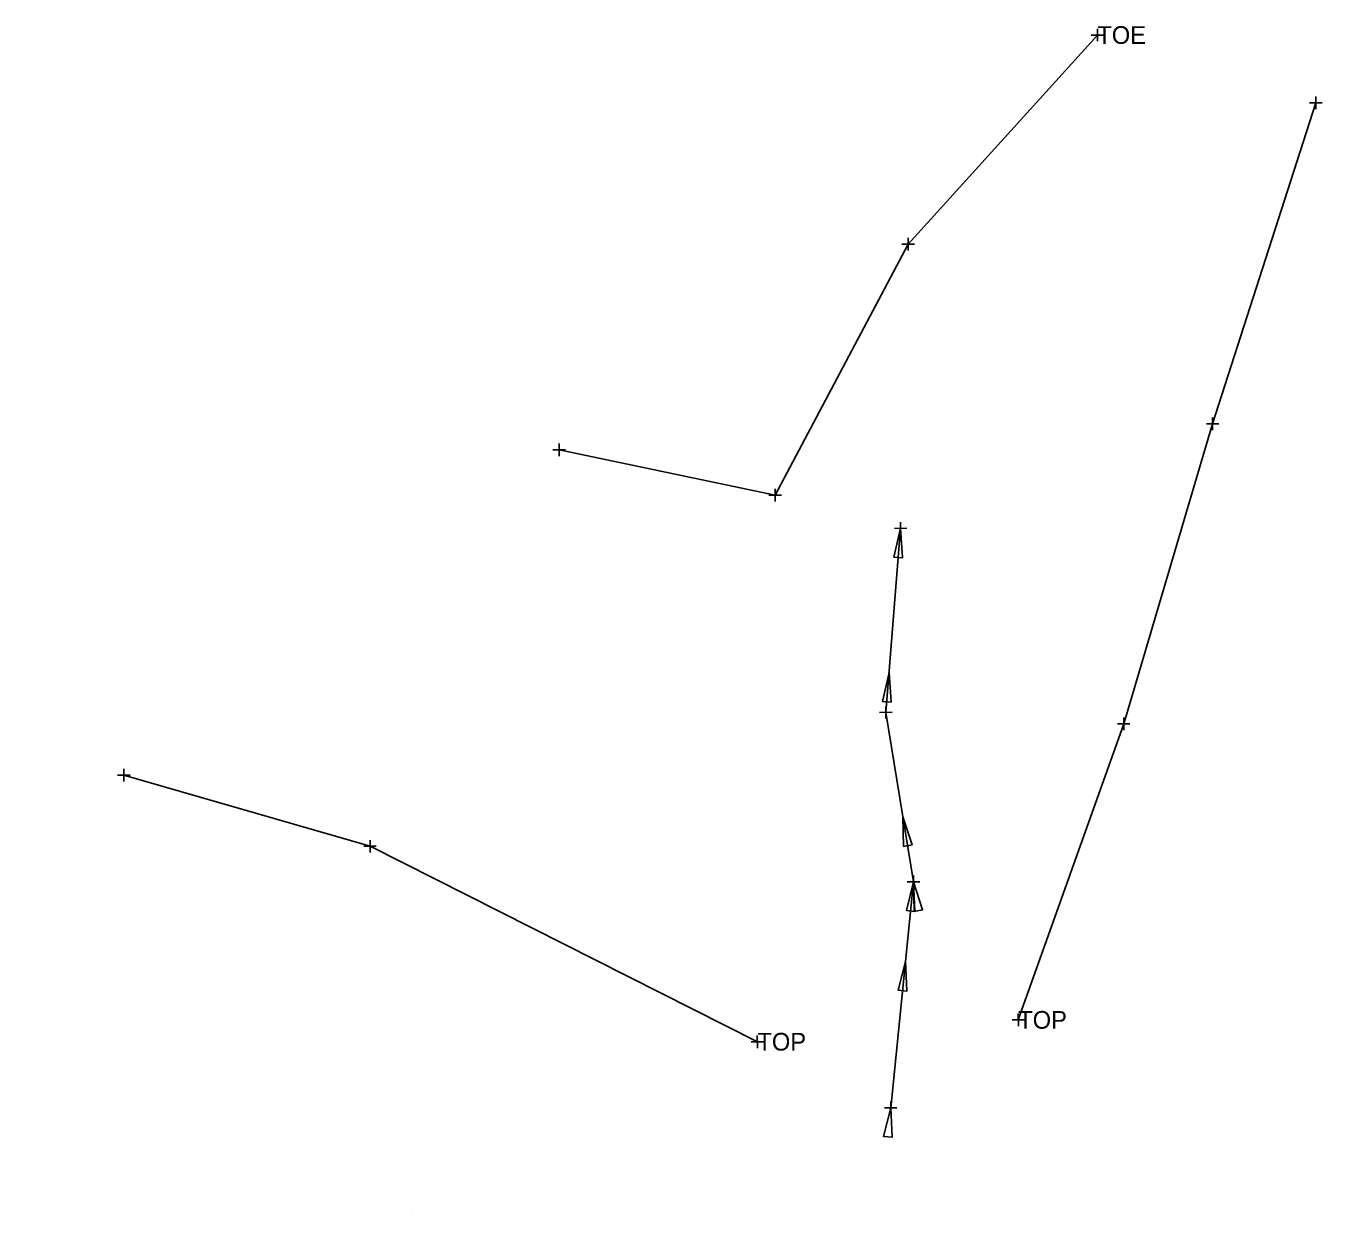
# Model space of a CAD drawing. Extents: x 1733239 to 1734352, y 466612 to 468622.
# Drawn here: x 1733857.5 to 1733989.3, y 468164.4 to 468284.8 of the extents above; entities that cross this region are included whole.
import ezdxf

# ---------------------------------------------------------------- set-up
doc = ezdxf.new("R2010")
doc.units = 0
for name, color, linetype in [('S_Terrain_Holes', 7, 'Continuous'), ('S_Terrain_Major_Contours', 7, 'Continuous'), ('S_Terrain_Minor_Contours', 7, 'Continuous'), ('S_Terrain_Voids', 7, 'Continuous'), ('S_Traffic_Sign_SinglePost', 7, 'Continuous')]:
    doc.layers.add(name, color=color, linetype=linetype)

msp = doc.modelspace()

# ---------------------------------------------------------------- linework, layer by layer
at = {"layer": 'S_Terrain_Holes'}
for points in [[(1733966.4, 468283.88), (1733947.16, 468262.61), (1733933.64, 468237.12), (1733911.68, 468241.73)], [(1733958.36, 468183.78), (1733969.08, 468213.87), (1733978.12, 468244.35), (1733988.61, 468276.99)], [(1733931.84, 468181.56), (1733892.45, 468201.42), (1733867.42, 468208.66)]]:
    msp.add_lwpolyline(points, dxfattribs=at)
at = {"layer": 'S_Terrain_Major_Contours'}
for p, q in [((1733922.19, 468262.45), (1733922.19, 468262.45)), ((1733857.46, 468168.99), (1733857.46, 468168.99)), ((1733950.29, 468167.39), (1733950.29, 468167.39)), ((1733896.74, 468164.45), (1733896.74, 468164.45))]:
    msp.add_line(p, q, dxfattribs=at)
at = {"layer": 'S_Terrain_Minor_Contours'}
for p, q in [((1733965.77, 468283.88), (1733967.04, 468283.88)), ((1733966.4, 468283.24), (1733966.4, 468284.51)), ((1733966.4, 468283.88), (1733966.4, 468283.88)), ((1733988.62, 468276.36), (1733988.61, 468277.63)), ((1733987.98, 468276.99), (1733989.25, 468276.99)), ((1733988.61, 468276.99), (1733988.61, 468276.99)), ((1733947.17, 468261.98), (1733947.16, 468263.25)), ((1733946.53, 468262.61), (1733947.8, 468262.62)), ((1733947.16, 468262.61), (1733947.16, 468262.61)), ((1733977.49, 468244.35), (1733978.76, 468244.36)), ((1733978.12, 468243.72), (1733978.12, 468244.99)), ((1733978.12, 468244.35), (1733978.12, 468244.35)), ((1733911.04, 468241.73), (1733912.31, 468241.73)), ((1733911.68, 468241.09), (1733911.68, 468242.37)), ((1733911.68, 468241.73), (1733911.68, 468241.73)), ((1733933.64, 468236.48), (1733933.64, 468237.76)), ((1733933, 468237.12), (1733934.28, 468237.12)), ((1733933.64, 468237.12), (1733933.64, 468237.12)), ((1733946.39, 468233.11), (1733946.39, 468234.38)), ((1733945.76, 468233.74), (1733947.03, 468233.75)), ((1733946.39, 468233.75), (1733946.39, 468233.75)), ((1733944.9, 468214.4), (1733944.89, 468215.67)), ((1733944.26, 468215.03), (1733945.53, 468215.04)), ((1733944.9, 468215.03), (1733944.9, 468215.03)), ((1733969.08, 468213.23), (1733969.08, 468214.51)), ((1733968.44, 468213.87), (1733969.72, 468213.87)), ((1733969.08, 468213.87), (1733969.08, 468213.87)), ((1733867.42, 468208.02), (1733867.42, 468209.29)), ((1733866.78, 468208.66), (1733868.05, 468208.66)), ((1733867.42, 468208.66), (1733867.42, 468208.66)), ((1733891.82, 468201.42), (1733893.09, 468201.43)), ((1733892.45, 468200.79), (1733892.45, 468202.06)), ((1733892.45, 468201.42), (1733892.45, 468201.42)), ((1733947.72, 468197.17), (1733947.72, 468198.45)), ((1733947.72, 468197.17), (1733947.72, 468198.45)), ((1733947.08, 468197.81), (1733948.36, 468197.81)), ((1733947.08, 468197.81), (1733948.36, 468197.81)), ((1733947.72, 468197.81), (1733947.72, 468197.81)), ((1733947.72, 468197.81), (1733947.72, 468197.81)), ((1733957.73, 468183.78), (1733959, 468183.78)), ((1733958.37, 468183.15), (1733958.36, 468184.42)), ((1733958.36, 468183.78), (1733958.36, 468183.78)), ((1733931.2, 468181.56), (1733932.47, 468181.56)), ((1733931.84, 468180.92), (1733931.83, 468182.19)), ((1733931.84, 468181.56), (1733931.84, 468181.56)), ((1733944.75, 468174.85), (1733946.03, 468174.85)), ((1733945.39, 468174.21), (1733945.39, 468175.48)), ((1733945.39, 468174.85), (1733945.39, 468174.85))]:
    msp.add_line(p, q, dxfattribs=at)
at = {"layer": 'S_Terrain_Voids'}
for p, q in [((1733946.39, 468233.75), (1733946.39, 468233.75)), ((1733945.22, 468219.08), (1733945.22, 468219.08)), ((1733946.64, 468204.41), (1733946.64, 468204.41)), ((1733947.72, 468197.81), (1733947.72, 468197.81)), ((1733947.72, 468197.81), (1733947.72, 468197.81)), ((1733946.9, 468189.7), (1733946.9, 468189.7)), ((1733945.39, 468174.85), (1733945.39, 468174.85))]:
    msp.add_line(p, q, dxfattribs=at)
for points in [[(1733946.39, 468233.75), (1733944.9, 468215.03), (1733947.72, 468197.81)], [(1733945.39, 468174.85), (1733947.72, 468197.81)]]:
    msp.add_lwpolyline(points, dxfattribs=at)
for points in [[(1733946.39, 468233.75), (1733946.6, 468230.75), (1733945.71, 468230.82)], [(1733945.22, 468219.08), (1733945.43, 468216.08), (1733944.54, 468216.15)], [(1733946.64, 468204.41), (1733947.56, 468201.56), (1733946.68, 468201.41)], [(1733947.72, 468197.81), (1733947.86, 468194.81), (1733946.98, 468194.9)], [(1733947.72, 468197.81), (1733948.64, 468194.95), (1733947.76, 468194.81)], [(1733946.9, 468189.7), (1733947.04, 468186.7), (1733946.16, 468186.79)], [(1733945.39, 468174.85), (1733945.53, 468171.85), (1733944.65, 468171.94)]]:
    msp.add_lwpolyline(points, close=True, dxfattribs=at)

# ---------------------------------------------------------------- texts
at = {"layer": 'S_Traffic_Sign_SinglePost'}
for s, p in [('TOE', (1733966.4, 468282.98)), ('TOP', (1733958.36, 468182.88)), ('TOP', (1733931.84, 468180.66))]:
    msp.add_text(s, height=1.8, dxfattribs=at).set_placement(p)

doc.saveas('drawing.dxf')
